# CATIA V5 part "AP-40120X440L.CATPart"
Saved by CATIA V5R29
Part number: AP-40120X440L
Source: Unknown
Bounding box of the stored display mesh (mm): x -220 to 220, y -60 to 60, z -20 to 20
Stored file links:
  C:\가치같이\SmartFactory_BoxErectorConveyor\Boxing(under)\AP-40120X440L.CATPart
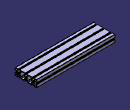
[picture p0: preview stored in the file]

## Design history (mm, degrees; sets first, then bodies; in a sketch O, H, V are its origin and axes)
Body1 (main body)
  Solid1 "PartBody": solid without history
